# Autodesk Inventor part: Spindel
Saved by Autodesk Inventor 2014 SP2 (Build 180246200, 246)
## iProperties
Created: 2015-06
Part Number: Spindel
Material: Generisch
Document SubType Name: Modeling
Designer: e_krauts
Density: 1 g/cm^3
Appearance: Vorgabe
Author: e_krauts
Sending System: SolidWorks 2011
Last Author: e_boekem
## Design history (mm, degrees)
node "Spindel.ipt1"
node "Aufsatz-Linear austragen2"
node "Basis1"
